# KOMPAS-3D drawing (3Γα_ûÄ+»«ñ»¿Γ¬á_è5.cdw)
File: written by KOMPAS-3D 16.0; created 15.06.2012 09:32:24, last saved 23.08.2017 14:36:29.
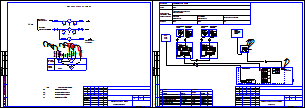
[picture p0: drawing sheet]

Sheets 1-2: A3, landscape

Title block, sheet 1: name: г. Москва, ул. Нежинская, д. 14, к.8 (кв. 1 и кв. 2); sheet number: 1; sheets: 27 / 28; sheet format: A3; stored path: D:\Проекты\Лыткарино\ул. Квартал 3А, д.25\710.74 РП.cdw; cell 320: Р
Title block, sheet 2: sheet number: 2

Views: Вид 2, Вид 3, Вид 4, Вид 5
Referenced files in C:\Program Files (x86)\ASCON\KOMPAS-3D V16\Sys\: SPDS.lcs, EngSys.lcs, GRAPHIC.LHS
Referenced files: graphic.tdp
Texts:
  МО, Клинский район, д. Решетниково, ул. Центральная, д.14
  GOST Common
  Normal
  List Paragraph
  heading 3
  для схемы
  txt
  краны
  Фоновая заливка
  Т0-элементы
  ВРУ
  Плата подключений
  СБ МКТС
  приборы
  по месту
  Преобразователь расхода
  Термопреобразователь
  Преобразователь давления
  Преобразователь цифровой
  Системный блок МКТС
  шкаф
  учета
  UQIES
  Подающий
  трубопровод
  Обратный
  УУТЭ
  Функциональная схема
  Трубопровод
  подпитки
  Клемная колодка
  Счетчик
  расхода воды
  с импульсным
  выходом
  каб.
  Начало
  трассы
  Трассы
  Марка
  Проложен
  Датчик температуры (Т1)
  Датчик температуры (Т2)
  Датчик давления (Т1)
  Датчик давления (Т2)
  Изм. модуль (Т1)
  Изм. модуль (Т2)
  Изм. модуль (Т94)
  ВРУ 220В, 50 Гц
  ИМ1 УУТЭ
  ИМ2 УУТЭ
  ИМ (Т1)
  FTP
  ПВС
  Конец
  Кол-во и
  сеч. жил
  Длина,
  Агрегат
  Системный блок  МКТС
  Среда
  Вода
  параметра и место
  отбора импульса
  Учет тепловой энергии и
  теплоносителя
  Трубопровод подпитки
  ИМ1
  ИМ2
  ИМ3
  Pt 100
  Преобразователь
  температуры
  давления
  UP+
  UP-
  ИМП
  Лин
  Измерительный
  модуль М121
  Размеры, параметризация
  сит. план
  подача ГВС
  обратка ГВС
  хвс
  обратка
  POLYLINE_STYLE_0.25_RGB_0_0_0
  стены
  Основная (не является границей для штриховки)
  POLYLINE_STYLE_0.18_RGB_0_0_0
  ХВС
  зеленая
  Красная тонкая
  арматура
  Подача
  Скрытая линия
  Ось Z
  Ось Y
  Ось X
  Образующая трубопровода (проектируемого)
  Трубопровод толщиной 0.6мм (одна линия)
  Трубопровод толщиной 1.2мм (одна линия)
  Трубопровод толщиной 1.0мм (одна линия)
  Трубопровод толщиной 0.8мм (одна линия)
  Трубопровод существующий (одна линия)
  Трубопровод невидимый (одна линия)
  Трубопровод демонтируемый (одна линия)
  Осевая трубопровода
  Осевая трубопровода (демонтируемого)
  Образующая трубопровода (существующего)
  Образующая трубопровода (невидимого)
  Изолированный трубопровод проектируемый (одна линия)
  Изолированный трубопровод существующий (одна линия)
  Образующая изоляции
  Изоляция
  Изолированный трубопровод невидимый (одна линия)
  Штрих пвс 075
  штрих пвс 2,5
  существующее оборудование
  Существующее оборудование
  K5LT_BASIC_RGB_0_0_255_THICK_0.53
  POLYLINE_STYLE_1.51_RGB_0_0_255
  POLYLINE_STYLE_0.50_RGB_128_128_128
  K5LT_AXLED_RGB_255_128_0_SC_1_THICK_0.18
  ACAD_ISO04W100_RGB_0_0_0_SC_1_THICK_0.18
  тонкая черная
  пломбировка
  Провода
  синий штрих
  Стили документа
  G2co
  расход вторичной воды объемный
  расход вторичной воды объемный при 70гр
  Gco
  расход теплоносителя массовый
  расход теплоносит объемн подающ
  расход теплоносит объемн обр
  Лапир
  Ghvs
  Im1
  Im2
  Im3
  Im4
  Im5
  Khvs
  норматив ХВС
  число подъездов
  число этажей
  Nkv
  число квартир
  тепловая нагрузка на отопление
  сумма Q
  Qgvs
  тепловая нагрузка ГВС
  тепловая нагрузка на циркуляцию ГВС
  иммитовставка или под манометр
  ro1
  ro2
  ro3
  ro4
  верх предел темп граф
  нижн предел темп граф
  темп подачи ГВС
  темп обр ГВС
  темр хол воды
  vzdh
  Kchn
  Ktp
  Knp
  beta
  tnv
  Vклап
  KLP
  RPD
  RDS
  PUMP
  ro5
  Переход К-76 x 3-38 x 2-09Г2С ГОСТ 17378-2001
  Переход ГОСТ 17378-2001
  Переход
  ГОСТ
  Сталь 09Г2С ГОСТ 19281-89
  Переход К-76 x 3-45 x 2,5-09Г2С ГОСТ 17378-2001
  Переход К-57 x 3-38 x 2-09Г2С ГОСТ 17378-2001
  Переход К-57 x 3-32 x 2-09Г2С ГОСТ 17378-2001
  Втулка 20x50
  Переход К-108 x 4-57 x 3-09Г2С ГОСТ 17378-2001
  Переход К-45 x 2,5-32 x 2-09Г2С ГОСТ 17378-2001
  Переход К-89 x 3,5-45 x 2,5-09Г2С ГОСТ 17378-2001
  Переход К-133 x 5-108 x 4-09Г2С ГОСТ 17378-2001
  Переход К-159 x 4,5-89 x 3,5-09Г2С ГОСТ 17378-2001
  Переход К-45 x 2,5-38 x 2-09Г2С ГОСТ 17378-2001
  Фланец 1-32-1 Ст3сп ГОСТ 12820-80
  Фланцы
  Фланец
  квадратный
  Ст3сп
  Ст3сп ГОСТ 380-2005
  Переход К-57 x 3-45 x 2,5-09Г2С ГОСТ 17378-2001
  Переход К-76 x 3-57 x 3-09Г2С ГОСТ 17378-2001
  Фланец 1-50-16 Ст3сп ГОСТ 12821-80
  Переход К-89 x 3,5-76 x 3,5-09Г2С ГОСТ 17378-2001
  Переход К-108 x 4-89 x 3,5-09Г2С ГОСТ 17378-2001
  Тройник 159 x 4,5-09Г2С ГОСТ 17376-2001
  Тройники ГОСТ 17376-2001
  Тройник
  Отвод 90-159 x 4-09Г2С ГОСТ 17375-2001
  Отвод ГОСТ 17375-2001
  Отвод
  Переход К-108 x 4-76 x 3,5-09Г2С ГОСТ 17378-2001
  Переход К-159 x 4,5-108 x 4-09Г2С ГОСТ 17378-2001
  Переход К-133 x 5-76 x 3,5-09Г2С ГОСТ 17378-2001
  Переход К-133 x 4-89 x 3,5-09Г2С ГОСТ 17378-2001
  Переход К-1-42,4 x 2,6-21,3 x 2-TS10 ГОСТ 17378-2001
  TS10
  Сталь TS10 ИСО 2604/2-75
  Фланец 1-20-16 Ст3сп ГОСТ 12820-80
  Лит-Масса-Масштаб
  Материал-Предприятие
  Title Specification
  Body Specification ( left align )
  Body Specificaton ( centered )
  Поз.
  Кол.
  Приме-
  чание
  Таблица спецификации
  Засыпка
  Штрих3
  Штрих2
  Штрих1
  Песок
  Штр0.5пр7
  Штр0.5пр12
  Штр0.3пр10
  Штр1.4пр21.21
  Штр1пр15
  Штр2.12пр35
  Штр1.5пр25
  Штр2.82пр42.42
  Штр2пр30
  SACNCR_ISO 1
  Электрощитовая
  Пр-1
  Ок-1
  вапвыапвы
  Обозначение стандарта
  Типоразмер
  Разраб.
  Пров.
  Т.контр.
  Н.контр.
  Утв.
  автоматизации
  Рабочие чертежи основного комплекта. ГОСТ Р 21.1101-2009 Ф3
  Стадия
  Лист
  Листов
  Изм.
  Кол.уч.
  №док.
  Подп.
  Дата
  Изменение
  Номер документа
  Подпись
  Наименование объекта строительства, в состав которого входит здание, наим. микр
  Наименование здания (сооружения)
  Порядковый номер листа
  Количество листов в документе
  Наименование изображения
  Индекс предприятия, выпускающего документ
  Инв. № подл.
  Подп. и дата
  Взам. инв. №
  Инвентарный номер подлинника
  Подпись принявшего подлинник на хранение
  Инвентарный номер подлинника, взамен которого выпущен данный подлинник
  Согласовано
  Формат листа
  Согласование
  03 Рабочие чертежи основного комплекта. ГОСТ Р 21.1101-2009 Ф3
  Схема соединений внешних
  проводок
Dimensions and other numbers on the sheet: 0; 220В; 50Гц; 1; 2; 3; 6; 5; 4; 10; 1,2,3; 4,5; 6,7; 8,9; 7; 8; 9; 10,4; 12,6520; 0,1050; 105; 120; 12,2518; 9,3; 70; 2x2x0,52; 3х0,75; 4-20; 09Г2С; 12; 16; 17; 19; 20; 21; 22; 23; 24; 25; 26; 30; 31; 33; 34; 52; 64; 65; 66; 67; 69; 71; 72; 73; 74; 75; 27; 28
